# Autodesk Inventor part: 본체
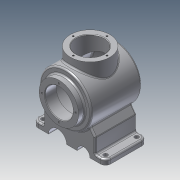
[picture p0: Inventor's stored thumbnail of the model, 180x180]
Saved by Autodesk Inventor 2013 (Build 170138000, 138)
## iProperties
Created: 2018-08
Part Number: 본체
Material: 알루미늄 6061
Document SubType Name: Modeling
Designer: Administrator
Mass: 1886 g
Surface Area: 1087.42 cm^2
Volume: 695.939 cm^3
Density: 2.71 g/cm^3
Author: Administrator
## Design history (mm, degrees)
sketch "스케치1"
  geometry: L1 (0, 0)-(0, 50); L2 (0, 50)-(96.671, 50); L3 (0, 0)-(108, 0); A1 r 116 centre (-8, 0) between (108, 0) and (96.671, 50); 1 further point
  constraints: 6 end point, 2 coincident, 2 horizontal alignment, 2 point on circle, 1 centre point, 1 parallel, 1 perpendicular, 1 vertical
  dimensions: "d0" = 50 distance of L1.start L1.end; "d2" = 108 distance of L3.end L1.start; "d3" = 116 radius of A1
revolve "회전1" sketch "스케치1" stored, may be unused: angle "d4" = 90 deg
feature "쉘1" dims "d5" = 10
node "작업 평면1"
sketch "스케치2"
  geometry: C1 r 38 at (0, 0); 1 further point
  constraints: 1 centre point, 1 coincident
  dimensions: "d7" = 76 diameter of C1
extrude "돌출1" join sketch "스케치2" stored distance "d8" = 10; taper "d9" = 0 deg
sketch "스케치3"
  geometry: C1 r 38 at (0, 0) reference; C2 r 27 at (0, 0)
  constraints: 1 centre point, 1 coincident
  dimensions: "d10" = 54 diameter of C2
extrude "돌출2" cut sketch "스케치3" stored distance "d11" = 10; taper "d12" = 0 deg
node "작업 평면2"
sketch "스케치4"
  geometry: L1 (-96.671, 50)-(-96.671, -50) reference; L2 (0, 50)-(0, -50) reference; L3 (0, -50)-(-96.671, -50) reference; C1 r 38 at (-48.335, 0); 3 further points
  constraints: 2 midpoint, 1 centre point, 1 horizontal alignment, 1 vertical alignment
  dimensions: "d14" = 76 diameter of C1
extrude "돌출3" join sketch "스케치4" stored distance "d15" = 10; taper "d16" = 0 deg
node "작업 평면3"
sketch "스케치5"
  geometry: L1 (82, 70)-(72, 70); L2 (72, 70)-(72, 50); L3 (82, 70)-(82, -70); L4 (82, -70)-(72, -70); L5 (72, -70)-(72, -50); L6 (72, -70)-(29.59, -40.304); L7 (72, -70)-(123.773, -70); L8 (72, 70)-(29.59, 40.304); L9 (72, 70)-(123.773, 70); L10 (72, 50)-(43.437, 50); L11 (72, -50)-(43.437, -50); A1 r 50 centre (0, 0) between (29.59, -40.304) and (29.59, 40.304) reference; 2 further points
  constraints: 22 end point, 3 horizontal, 3 perpendicular, 2 equal length, 2 parallel, 2 point on circle, 2 point on line, 1 horizontal alignment, 1 midpoint
  dimensions: "d18" = 10 distance between parallel lines of L2 L3; "d20" = 140 distance of L1.start L3.end; "d21" = 10 distance between parallel lines of L3 L5; "d22" = 20 distance of L4.end L5.end; "d23" = 20 distance of L1.end L2.end; "d25" = 82 distance of point (0, 0) point (82, 0); "d26" = 145 deg angle of L7 L6; "d28" = 145 deg angle of L8 L9
extrude "돌출4" join sketch "스케치5" distance "d29" = 80; taper "d30" = 0 deg
sketch "스케치6"
  geometry: L1 (-70, -82)-(70, -82) reference; C1 r 12.5 at (-27.5, -82); C2 r 17.5 at (22.5, -82); A1 r 50 centre (0, 0) between (-40.304, -29.59) and (40.304, -29.59) reference
  constraints: 2 centre point, 2 point on line
  dimensions: "d31" = 25 diameter of C1; "d32" = 35 diameter of C2; "d33" = 27.5 horizontal distance of A1.centre C1.centre; "d34" = 22.5 horizontal distance of A1.centre C2.centre
extrude "돌출5" cut sketch "스케치6" stored distance "d35" = 80; taper "d36" = 0 deg
sketch "스케치7"
  geometry: C1 r 27 at (0, 0) reference; 1 further point
  constraints: 1 vertical alignment
  dimensions: "d37" = 32.5 distance of point (0, 32.5) C1.centre
hole "구멍1" sketch "스케치7" at (0, 32.5) diameter "d38" = 3.242; stored, may be unused: countersink angle "d42" = 90 deg, drill point angle "d44" = 118 deg; dims "d39" = 8, "d40" = 4, "d41" = 2, "d43" = 10
sketch "스케치8"
  geometry: C1 r 38 at (0, 0) reference; C2 r 27 at (0, 0); 1 further point
  constraints: 1 centre point, 1 coincident
  dimensions: "d48" = 54 diameter of C2
extrude "돌출6" cut sketch "스케치8" stored distance "d49" = 80; taper "d50" = 0 deg
sketch "스케치9"
  geometry: C1 r 27 at (0, 0) reference; 2 further points
  constraints: 1 vertical alignment
  dimensions: "d51" = 32.5 distance of point (0, 32.5) C1.centre
hole "구멍2" sketch "스케치9" at (0, 32.5) diameter "d52" = 3.242; stored, may be unused: countersink angle "d56" = 90 deg, drill point angle "d58" = 118 deg; dims "d53" = 8, "d54" = 4, "d55" = 2, "d57" = 10
fillet "모깎기1" dims "d62" = 10
sketch "스케치10"
  geometry: C1 r 4 at (70, -10); C2 r 4 at (10, -10); A1 r 10 centre (70, -10) between (70, -20) and (80, -10) reference; A2 r 10 centre (10, -10) between (0, -10) and (10, -20) reference; 1 further point
  constraints: 2 centre point, 2 coincident
  dimensions: "d63" = 8 diameter of C1; "d64" = 8 diameter of C2
extrude "돌출7" cut sketch "스케치10" stored distance "d65" = 80; taper "d66" = 0 deg
chamfer "모따기1" distance "d67" = 1; stored, may be unused: second distance "d68" = 2, angle "d69" = 45 deg
fillet "모깎기2" dims "d70" = 3
fillet "모깎기3" dims "d71" = 3
fillet "모깎기4" dims "d72" = 3
fillet "모깎기5" dims "d73" = 3
fillet "모깎기6" dims "d74" = 3
node "작업 평면4"
sketch "스케치11"
  geometry: C1 r 32.5 at (0, 0); 1 further point
  constraints: 1 centre point, 1 coincident, 1 other
  dimensions: "d76" = 65 diameter of C1
feature "엠보싱1" sketch "스케치11" dims "d12" = 0, "d77" = 0.5, "d78" = 0
node "솔리드1"
pattern_circular "원형 패턴1" dims angle "d46" = 360 deg
pattern_circular "원형 패턴2" dims angle "d60" = 360 deg
mirror "대칭1"
other parameters: "d6" = 12, "d13" = 65, "d17" = 8
